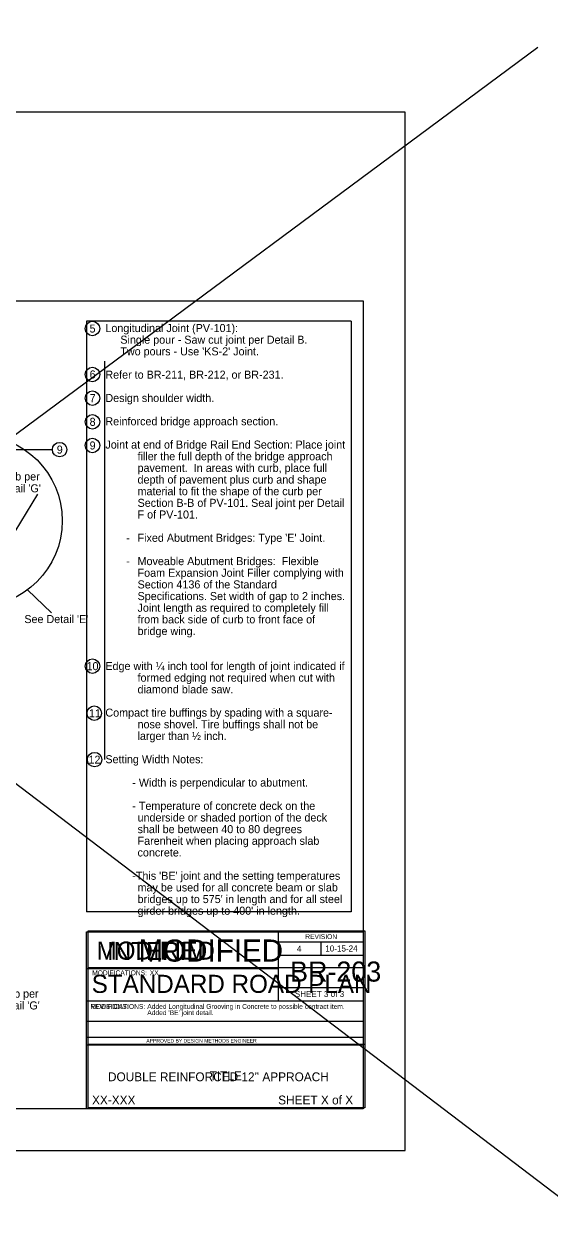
# Model space of a CAD drawing. Extents: x 8925 to 81668, y 4369 to 11918.
# Drawn here: x 19595 to 20902, y 4427 to 7423 of the extents above; entities that cross this region are included whole.
import ezdxf

# ---------------------------------------------------------------- set-up
doc = ezdxf.new("R2010")
doc.units = 0
for name, color, linetype in [('dsnCellElements', 7, 'Continuous'), ('dsnNonPlotable', 7, 'Continuous'), ('dsnShtPlotShapeBatchPrint', 7, 'Continuous'), ('dsnStdBlock', 7, 'Continuous'), ('dsnstdblockInterim', 7, 'Continuous'), ('dsnStdBlockModified', 7, 'Continuous'), ('dsnStdBlockNotModified', 7, 'Continuous'), ('dsnStdBorder', 7, 'Continuous'), ('dsnStdLabel', 7, 'Continuous'), ('dsnstdModifiedBlock', 7, 'Continuous'), ('Level 1', 7, 'Continuous'), ('SheetBorder', 7, 'Continuous')]:
    doc.layers.add(name, color=color, linetype=linetype)

msp = doc.modelspace()

# ---------------------------------------------------------------- linework, layer by layer
at = {"layer": 'dsnStdBlock'}
msp.add_lwpolyline([(17303, 6733.9), (20438, 6733.9), (20438, 4723.9), (17303, 4723.9)], close=True, dxfattribs=at)
at = {"layer": 'dsnStdBlockModified'}
for p, q in [((19750, 6683.9), (19750, 5213.9)), ((20408, 6683.9), (19750, 6683.9)), ((20408, 6683.9), (20408, 5213.9)), ((19795, 6583.9), (19795, 5592.4)), ((20408, 5213.9), (19750, 5213.9))]:
    msp.add_line(p, q, dxfattribs=at)
at = {"layer": 'dsnStdBlockNotModified'}
msp.add_lwpolyline([(17198.5, 4619.4), (20542.5, 4619.4), (20542.5, 7203.4), (17198.5, 7203.4)], close=True, dxfattribs=at)
at = {"layer": 'dsnStdBorder'}
for p, q in [((19557.3, 6364.4), (19665.3, 6364.4)), ((19572.7, 6160.4), (19628.8, 6252.8)), ((19603.1, 6014.7), (19663.4, 5957.9))]:
    msp.add_line(p, q, dxfattribs=at)
for centre, radius in [((19765, 6665.3), 18), ((19765, 6551), 18), ((19765, 6492), 18), ((19765, 6433.1), 18), ((19475.7, 6186.9), 214.2), ((19683.3, 6364), 18), ((19765, 6374.3), 18), ((19765, 5825.1), 18), ((19769.6, 5708), 18), ((19770.4, 5592.5), 18)]:
    msp.add_circle(centre, radius, dxfattribs=at)
at = {"layer": 'dsnstdModifiedBlock'}
for p, q in [((19754.3, 5074.8), (20442.4, 5074.8)), ((19754.3, 4884.8), (20442.4, 4884.8))]:
    msp.add_line(p, q, dxfattribs=at)
msp.add_lwpolyline([(19754.3, 5166.2), (20442.4, 5166.2), (20442.4, 4726.2), (19754.3, 4726.2)], close=True, dxfattribs=at)
at = {"layer": 'Level 1'}
for p, q in [((20227.1, 5163.9), (20227.1, 5072.6)), ((20227.1, 5139), (20438, 5139)), ((20332.6, 5139), (20332.6, 5105.8)), ((20227.1, 5105.8), (20438, 5105.8)), ((19750, 5072.6), (20227.1, 5072.6)), ((20227.1, 5072.6), (20227.1, 4992.6)), ((20438, 5024.8), (20227.1, 5024.8)), ((19750, 4992.6), (20438, 4992.6)), ((19750, 4941.6), (20438, 4941.6)), ((19750, 4901.6), (20438, 4901.6)), ((19750, 4882.6), (20438, 4882.6))]:
    msp.add_line(p, q, dxfattribs=at)
msp.add_lwpolyline([(19750, 5163.9), (20438, 5163.9), (20438, 4723.9), (19750, 4723.9)], close=True, dxfattribs=at)
msp.add_lwpolyline([(19750, 5163.9), (20438, 5163.9), (20438, 4723.9), (19750, 4723.9)], close=True, dxfattribs=at)
at = {"layer": 'SheetBorder'}
for p, q in [((17092.5, 7422.9), (21027.2, 4427.1)), ((20872.2, 7364.8), (17082.8, 4553.2))]:
    msp.add_line(p, q, dxfattribs=at)

# ---------------------------------------------------------------- texts
at = {"layer": 'dsnCellElements'}
for s, height, p in [('MODIFIED', 45, (19775.1, 5094.7)), ('MODIFICATIONS:', 12, (19760, 4972.2))]:
    msp.add_text(s, height=height, dxfattribs=at).set_placement(p)
at = {"layer": 'dsnNonPlotable'}
msp.add_text('REVISIONS:', height=12, dxfattribs=at).set_placement((19760, 4972.2))
at = {"layer": 'dsnShtPlotShapeBatchPrint'}
for s, p in [('10', (19750.2, 5815.1)), ('11', (19756.1, 5697.8)), ('12', (19755.1, 5582.4))]:
    msp.add_text(s, height=20, dxfattribs=at).set_placement(p)
at = {"layer": 'dsnstdblockInterim'}
msp.add_text('INTERIM', height=45, dxfattribs=at).set_placement((19801, 5093.6))
at = {"layer": 'dsnStdBorder'}
for s, p in [('Curb per', (19529.8, 6287.2)), ("Detail 'G'", (19529.8, 6257.7)), ("See Detail 'E'", (19595.6, 5932.3)), ('Curb per', (19527.1, 5000.2)), ("Detail 'G'", (19527.1, 4970.8))]:
    msp.add_text(s, height=20, dxfattribs=at).set_placement(p)
at = {"layer": 'dsnStdLabel'}
for s, p in [('5', (19757.8, 6655.3)), ('Longitudinal Joint (PV-101):', (19797.1, 6656.5)), ('     Single pour - Saw cut joint per Detail B.', (19797.1, 6627.5)), ("     Two pours - Use 'KS-2' Joint.", (19797.1, 6598.5)), ('6', (19757.9, 6541)), ('Refer to BR-211, BR-212, or BR-231.', (19797.1, 6540.5)), ('7', (19757.9, 6482)), ('Design shoulder width.', (19797.1, 6482.5)), ('8', (19757.9, 6423.1)), ('Reinforced bridge approach section.', (19797.1, 6424.5)), ('9', (19757.9, 6364.3)), ('Joint at end of Bridge Rail End Section: Place joint ', (19797.1, 6366.5)), ('9', (19676.2, 6354)), ('filler the full depth of the bridge approach ', (19877.1, 6337.5)), ('pavement.  In areas with curb, place full ', (19877.1, 6308.5)), ('depth of pavement plus curb and shape ', (19877.1, 6279.5)), ('material to fit the shape of the curb per ', (19877.1, 6250.5)), ('Section B-B of PV-101. Seal joint per Detail ', (19877.1, 6221.5)), ('F of PV-101.', (19877.1, 6192.5)), ('       -', (19797.1, 6134.5)), ("Fixed Abutment Bridges: Type 'E' Joint.", (19877.1, 6134.5)), ('       -', (19797.1, 6076.5)), ('Moveable Abutment Bridges:  Flexible ', (19877.1, 6076.5)), ('Foam Expansion Joint Filler complying with ', (19877.1, 6047.5)), ('Section 4136 of the Standard ', (19877.1, 6018.5)), ('Specifications. Set width of gap to 2 inches.  ', (19877.1, 5989.5)), ('Joint length as required to completely fill ', (19877.1, 5960.5)), ('from back side of curb to front face of ', (19877.1, 5931.5)), ('bridge wing.', (19877.1, 5902.5)), ('Edge with ¼ inch tool for length of joint indicated if ', (19797.1, 5815.5)), ('formed edging not required when cut with ', (19877.1, 5786.5)), ('diamond blade saw.', (19877.1, 5757.5)), ('Compact tire buffings by spading with a square-', (19797.1, 5699.5)), ('nose shovel. Tire buffings shall not be ', (19877.1, 5670.5)), ('larger than ½ inch.', (19877.1, 5641.5)), ('Setting Width Notes:', (19797.1, 5583.5)), ('         - Width is perpendicular to abutment.', (19797.1, 5525.5)), ('         - Temperature of concrete deck on the ', (19797.1, 5467.5)), ('underside or shaded portion of the deck ', (19877.1, 5438.5)), ('shall be between 40 to 80 degrees ', (19877.1, 5409.5)), ('Farenheit when placing approach slab ', (19877.1, 5380.5)), ('concrete.', (19877.1, 5351.5)), ("         -This 'BE' joint and the setting temperatures ", (19797.1, 5293.5)), ('may be used for all concrete beam or slab ', (19877.1, 5264.5)), ("bridges up to 575' in length and for all steel ", (19877.1, 5235.5)), ("girder bridges up to 400' in length.", (19877.1, 5206.5))]:
    msp.add_text(s, height=20, dxfattribs=at).set_placement(p)
at = {"layer": 'dsnstdModifiedBlock'}
for s, height, p in [('MODIFIED', 55, (19879.4, 5089.9)), ('MODIFICATIONS:', 12, (19764.3, 5056)), ('XX', 12, (19907.6, 5056)), ('TITLE', 22, (20056.4, 4794.5)), ('XX-XXX', 22, (19763.9, 4734.5)), ('SHEET X of X', 22, (20226.7, 4734.5))]:
    msp.add_text(s, height=height, dxfattribs=at).set_placement(p)
at = {"layer": 'Level 1'}
for s, height, p in [('REVISION', 12, (20294.1, 5146.1)), ('4', 15, (20273.4, 5114.5)), ('10-15-24', 15, (20343.9, 5115)), ('BR-203', 50, (20256.3, 5040.1)), ('STANDARD ROAD PLAN', 45.001, (19763.1, 5012)), ('SHEET 3 of 3', 15, (20268.1, 5001.9)), ('Added Longitudinal Grooving in Concrete to possible contract item. ', 12, (19901.3, 4972.3)), ("Added 'BE' joint detail.", 12, (19901.3, 4956.8)), ('APPROVED BY DESIGN METHODS ENGINEER', 9.003, (19899, 4888.4)), ("DOUBLE REINFORCED 12'' APPROACH", 22, (19803.5, 4792.2))]:
    msp.add_text(s, height=height, dxfattribs=at).set_placement(p)

doc.saveas('drawing.dxf')
